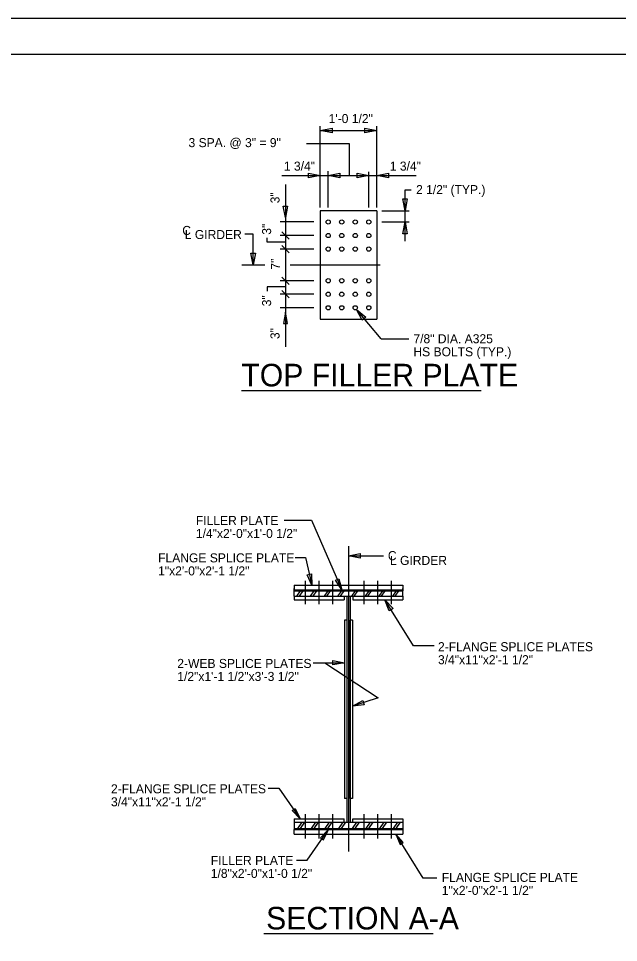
# Model space of a CAD drawing. Extents: x -448.1 to -400, y -140.7 to -111.4.
# Drawn here: x -434.2 to -423.13, y -128.41 to -111.36 of the extents above; entities that cross this region are included whole.
import ezdxf

# ---------------------------------------------------------------- set-up
doc = ezdxf.new("R2010")
doc.units = 0
for name, color, linetype in [('BR_AUTO DIMENSION', 7, 'Continuous'), ('BR_BORDER LINES', 7, 'Continuous'), ('BR_CENTER LINES', 7, 'Continuous'), ('BR_STRUCTURAL STEEL', 7, 'Continuous'), ('BR_TEXT', 7, 'Continuous'), ('Level 31', 7, 'Continuous')]:
    doc.layers.add(name, color=color, linetype=linetype)

msp = doc.modelspace()

# ---------------------------------------------------------------- linework, layer by layer
at = {"layer": 'BR_AUTO DIMENSION'}
for p, q in [((-428.633, -114.852), (-428.633, -113.35)), ((-427.591, -114.852), (-427.591, -113.35)), ((-428.633, -113.431), (-427.591, -113.431)), ((-428.487, -114.852), (-428.487, -114.184)), ((-427.737, -114.852), (-427.737, -114.192)), ((-429.345, -114.262), (-426.861, -114.262)), ((-429.275, -114.425), (-429.275, -117.42)), ((-427.069, -115.472), (-427.069, -114.527)), ((-427.069, -114.527), (-426.953, -114.527)), ((-427.496, -114.911), (-426.995, -114.911)), ((-428.751, -115.119), (-429.376, -115.119)), ((-427.496, -115.119), (-426.995, -115.119)), ((-429.871, -115.343), (-430.026, -115.343)), ((-429.871, -115.911), (-429.871, -115.343)), ((-428.751, -115.369), (-429.376, -115.369)), ((-429.209, -115.437), (-429.341, -115.302)), ((-429.209, -115.687), (-429.341, -115.552)), ((-428.751, -115.619), (-429.376, -115.619)), ((-428.751, -116.203), (-429.376, -116.203)), ((-429.209, -116.27), (-429.341, -116.135)), ((-429.209, -116.52), (-429.341, -116.385)), ((-428.751, -116.453), (-429.376, -116.453)), ((-428.751, -116.703), (-429.376, -116.703)), ((-427.506, -117.276), (-427.966, -116.736)), ((-427.506, -117.276), (-427, -117.276)), ((-429.3, -120.623), (-428.794, -120.623)), ((-428.794, -120.623), (-428.237, -121.906)), ((-429.099, -121.308), (-428.904, -121.308)), ((-428.904, -121.308), (-428.789, -121.823)), ((-426.911, -122.942), (-427.44, -122.089)), ((-426.53, -122.942), (-426.911, -122.942)), ((-428.766, -123.251), (-428.185, -123.251)), ((-428.546, -123.251), (-427.567, -123.899)), ((-427.567, -123.899), (-428.039, -124.056)), ((-429.593, -125.563), (-429.399, -125.563)), ((-429.399, -125.563), (-429.004, -126.13)), ((-428.875, -126.895), (-428.481, -126.328)), ((-426.735, -127.227), (-427.241, -126.412)), ((-429.069, -126.895), (-428.875, -126.895)), ((-426.479, -127.227), (-426.735, -127.227))]:
    msp.add_line(p, q, dxfattribs=at)
for points in [[(-428.416, -113.473), (-428.633, -113.431), (-428.416, -113.39)], [(-427.808, -113.39), (-427.591, -113.431), (-427.808, -113.473)], [(-428.849, -114.22), (-428.633, -114.262), (-428.849, -114.303)], [(-428.27, -114.303), (-428.487, -114.262), (-428.27, -114.22)], [(-427.954, -114.22), (-427.737, -114.262), (-427.954, -114.303)], [(-427.374, -114.303), (-427.591, -114.262), (-427.374, -114.22)], [(-427.028, -114.694), (-427.069, -114.911), (-427.111, -114.694)], [(-429.235, -114.828), (-429.275, -115.036), (-429.315, -114.828)], [(-427.111, -115.336), (-427.069, -115.119), (-427.028, -115.336)], [(-429.83, -115.694), (-429.871, -115.911), (-429.913, -115.694)], [(-429.31, -116.994), (-429.24, -116.994), (-429.275, -116.786)], [(-427.857, -116.928), (-427.966, -116.736), (-427.794, -116.874)], [(-427.895, -121.323), (-428.112, -121.281), (-427.895, -121.239)], [(-428.795, -121.611), (-428.789, -121.823), (-428.873, -121.629)], [(-428.352, -121.729), (-428.288, -121.702), (-428.237, -121.906)], [(-427.36, -122.294), (-427.44, -122.089), (-427.289, -122.25)], [(-428.402, -123.209), (-428.185, -123.251), (-428.402, -123.293)], [(-427.82, -124.027), (-428.039, -124.056), (-427.847, -123.948)], [(-429.152, -125.979), (-429.095, -125.94), (-429.004, -126.13)], [(-428.628, -126.48), (-428.571, -126.519), (-428.481, -126.328)], [(-427.161, -126.607), (-427.102, -126.571), (-427.241, -126.412)]]:
    msp.add_lwpolyline(points, close=True, dxfattribs=at)
for points in [[(-428.091, -114.262), (-428.091, -113.675), (-428.887, -113.675)], [(-429.275, -115.492), (-429.612, -115.492), (-429.612, -115.411)], [(-429.275, -116.316), (-429.612, -116.316), (-429.612, -116.398)], [(-428.112, -121.281), (-427.464, -121.281)]]:
    msp.add_lwpolyline(points, dxfattribs=at)
at = {"layer": 'BR_BORDER LINES'}
msp.add_line((-400.801, -112.031), (-445.689, -112.031), dxfattribs=at)
at = {"layer": 'BR_CENTER LINES'}
for p, q in [((-430.079, -115.911), (-429.656, -115.911)), ((-429.19, -115.911), (-427.528, -115.911)), ((-428.112, -121.098), (-428.112, -126.733))]:
    msp.add_line(p, q, dxfattribs=at)
at = {"layer": 'BR_STRUCTURAL STEEL'}
for p, q in [((-428.633, -114.911), (-428.633, -116.911)), ((-427.591, -114.911), (-428.633, -114.911)), ((-427.591, -114.911), (-427.591, -116.911)), ((-428.633, -116.911), (-427.591, -116.911)), ((-429.112, -121.823), (-429.112, -121.906)), ((-429.112, -121.823), (-427.112, -121.823)), ((-429.112, -122.026), (-429.112, -121.88)), ((-428.904, -122.172), (-428.904, -121.74)), ((-428.654, -122.172), (-428.654, -121.74)), ((-428.404, -122.172), (-428.404, -121.74)), ((-427.82, -122.172), (-427.82, -121.74)), ((-427.57, -122.172), (-427.57, -121.74)), ((-427.32, -122.172), (-427.32, -121.74)), ((-427.112, -121.823), (-427.112, -121.906)), ((-427.112, -122.026), (-427.112, -121.88)), ((-429.112, -121.906), (-429.112, -121.927)), ((-429.112, -121.906), (-427.112, -121.906)), ((-429.112, -121.927), (-427.112, -121.927)), ((-429.112, -122.026), (-427.112, -122.026)), ((-429.112, -122.026), (-429.112, -122.089)), ((-429.063, -122.026), (-428.995, -121.927)), ((-429.016, -122.026), (-428.948, -121.927)), ((-428.811, -122.026), (-428.743, -121.927)), ((-428.764, -122.026), (-428.696, -121.927)), ((-428.737, -121.906), (-427.487, -121.906)), ((-427.487, -121.927), (-428.737, -121.927)), ((-428.737, -122.026), (-428.195, -122.026)), ((-428.558, -122.026), (-428.49, -121.927)), ((-428.511, -122.026), (-428.443, -121.927)), ((-428.306, -122.026), (-428.238, -121.927)), ((-428.259, -122.026), (-428.191, -121.927)), ((-428.195, -122.026), (-428.195, -122.089)), ((-428.143, -122.026), (-428.143, -126.193)), ((-428.081, -122.026), (-428.081, -126.193)), ((-428.053, -122.026), (-427.985, -121.927)), ((-428.029, -122.026), (-428.029, -122.089)), ((-428.029, -122.026), (-427.487, -122.026)), ((-428.006, -122.026), (-427.938, -121.927)), ((-427.801, -122.026), (-427.733, -121.927)), ((-427.754, -122.026), (-427.686, -121.927)), ((-427.548, -122.026), (-427.48, -121.927)), ((-427.501, -122.026), (-427.433, -121.927)), ((-427.295, -122.026), (-427.228, -121.927)), ((-427.248, -122.026), (-427.181, -121.927)), ((-427.112, -121.906), (-427.112, -121.927)), ((-427.112, -122.026), (-427.112, -122.089)), ((-429.112, -122.089), (-428.195, -122.089)), ((-428.029, -122.089), (-427.112, -122.089)), ((-428.185, -122.464), (-428.185, -125.755)), ((-428.143, -122.464), (-428.185, -122.464)), ((-428.143, -122.464), (-428.143, -125.755)), ((-428.081, -125.755), (-428.081, -122.464)), ((-428.039, -122.464), (-428.081, -122.464)), ((-428.039, -122.464), (-428.039, -125.755)), ((-428.143, -125.755), (-428.185, -125.755)), ((-428.039, -125.755), (-428.081, -125.755)), ((-429.112, -126.13), (-429.112, -126.328)), ((-429.112, -126.13), (-428.195, -126.13)), ((-428.904, -126.495), (-428.904, -126.047)), ((-428.654, -126.495), (-428.654, -126.047)), ((-428.404, -126.495), (-428.404, -126.047)), ((-428.195, -126.193), (-428.195, -126.13)), ((-428.029, -126.193), (-428.029, -126.13)), ((-428.029, -126.13), (-427.112, -126.13)), ((-427.82, -126.495), (-427.82, -126.047)), ((-427.57, -126.495), (-427.57, -126.047)), ((-427.32, -126.495), (-427.32, -126.047)), ((-427.112, -126.13), (-427.112, -126.328)), ((-429.112, -126.193), (-427.112, -126.193)), ((-429.112, -126.308), (-427.112, -126.308)), ((-429.112, -126.412), (-429.112, -126.328)), ((-429.112, -126.328), (-427.112, -126.328)), ((-429.046, -126.308), (-428.968, -126.193)), ((-428.999, -126.308), (-428.921, -126.193)), ((-428.794, -126.308), (-428.715, -126.193)), ((-428.747, -126.308), (-428.668, -126.193)), ((-428.541, -126.308), (-428.463, -126.193)), ((-428.494, -126.308), (-428.416, -126.193)), ((-428.289, -126.308), (-428.21, -126.193)), ((-428.242, -126.308), (-428.163, -126.193)), ((-428.036, -126.308), (-427.958, -126.193)), ((-427.989, -126.308), (-427.911, -126.193)), ((-427.784, -126.308), (-427.705, -126.193)), ((-427.737, -126.308), (-427.658, -126.193)), ((-427.531, -126.308), (-427.453, -126.193)), ((-427.484, -126.308), (-427.406, -126.193)), ((-427.279, -126.308), (-427.2, -126.193)), ((-427.232, -126.308), (-427.153, -126.193)), ((-427.112, -126.328), (-427.112, -126.412)), ((-429.112, -126.412), (-427.112, -126.412))]:
    msp.add_line(p, q, dxfattribs=at)
for centre in [(-428.487, -115.119), (-428.487, -115.119), (-428.237, -115.119), (-428.237, -115.119), (-427.987, -115.119), (-427.987, -115.119), (-427.737, -115.119), (-427.737, -115.119), (-428.487, -115.369), (-428.487, -115.369), (-428.237, -115.369), (-428.237, -115.369), (-427.987, -115.369), (-427.987, -115.369), (-427.737, -115.369), (-427.737, -115.369), (-428.487, -115.619), (-428.487, -115.619), (-428.237, -115.619), (-428.237, -115.619), (-427.987, -115.619), (-427.987, -115.619), (-427.737, -115.619), (-427.737, -115.619), (-428.487, -116.203), (-428.487, -116.203), (-428.237, -116.203), (-428.237, -116.203), (-427.987, -116.203), (-427.987, -116.203), (-427.737, -116.203), (-427.737, -116.203), (-428.487, -116.453), (-428.487, -116.453), (-428.237, -116.453), (-428.237, -116.453), (-427.987, -116.453), (-427.987, -116.453), (-427.737, -116.453), (-427.737, -116.453), (-428.487, -116.703), (-428.487, -116.703), (-428.237, -116.703), (-428.237, -116.703), (-427.987, -116.703), (-427.987, -116.703), (-427.737, -116.703), (-427.737, -116.703)]:
    msp.add_circle(centre, 0.0391, dxfattribs=at)
at = {"layer": 'BR_TEXT'}
for p, q in [((-430.09, -118.227), (-425.665, -118.227)), ((-429.673, -128.247), (-426.551, -128.247))]:
    msp.add_line(p, q, dxfattribs=at)
at = {"layer": 'Level 31'}
msp.add_lwpolyline([(-448.133, -140.698), (-400.133, -140.698), (-400.133, -111.364), (-448.133, -111.364)], close=True, dxfattribs=at)

# ---------------------------------------------------------------- texts
at = {"layer": 'BR_TEXT'}
for s, height, p in [('1\'-0 1/2"', 0.1667, (-428.478, -113.294)), ('3 SPA. @ 3" = 9"', 0.16667, (-431.065, -113.738)), ('1 3/4"', 0.1667, (-429.305, -114.172)), ('1 3/4"', 0.1667, (-427.35, -114.172)), ('2 1/2" (TYP.)', 0.16667, (-426.865, -114.605)), ('C', 0.167, (-431.18, -115.359)), ('L GIRDER', 0.1667, (-431.134, -115.434)), ('7/8" DIA. A325', 0.16667, (-426.914, -117.357)), ('HS BOLTS (TYP.)', 0.16667, (-426.914, -117.597)), ('TOP FILLER PLATE', 0.41667, (-430.09, -118.153)), ('FILLER PLATE', 0.16667, (-430.929, -120.71)), ('1/4"x2\'-0"x1\'-0 1/2"', 0.16667, (-430.929, -120.95)), ('C', 0.167, (-427.385, -121.359)), ('FLANGE SPLICE PLATE', 0.16667, (-431.626, -121.4)), ('L GIRDER', 0.1667, (-427.347, -121.447)), ('1"x2\'-0"x2\'-1 1/2"', 0.16667, (-431.626, -121.64)), ('2-FLANGE SPLICE PLATES', 0.16667, (-426.46, -123.039)), ('2-WEB SPLICE PLATES', 0.16667, (-431.272, -123.348)), ('3/4"x11"x2\'-1 1/2"', 0.16667, (-426.46, -123.279)), ('1/2"x1\'-1 1/2"x3\'-3 1/2"', 0.16667, (-431.272, -123.588)), ('2-FLANGE SPLICE PLATES', 0.16667, (-432.496, -125.661)), ('3/4"x11"x2\'-1 1/2"', 0.16667, (-432.496, -125.901)), ('FILLER PLATE', 0.16667, (-430.654, -126.982)), ('1/8"x2\'-0"x1\'-0 1/2"', 0.16667, (-430.654, -127.222)), ('FLANGE SPLICE PLATE', 0.16667, (-426.39, -127.295)), ('1"x2\'-0"x2\'-1 1/2"', 0.16667, (-426.39, -127.535)), ('SECTION A-A', 0.41667, (-429.633, -128.173))]:
    msp.add_text(s, height=height, dxfattribs=at).set_placement(p)
for s, p in [('3"', (-429.385, -114.775)), ('3"', (-429.54, -115.354)), ('7"', (-429.378, -115.998)), ('3"', (-429.54, -116.675)), ('3"', (-429.385, -117.28))]:
    msp.add_text(s, height=0.1667, rotation=90, dxfattribs=at).set_placement(p)

doc.saveas('drawing.dxf')
